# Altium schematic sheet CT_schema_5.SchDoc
size 367 x 245 mm
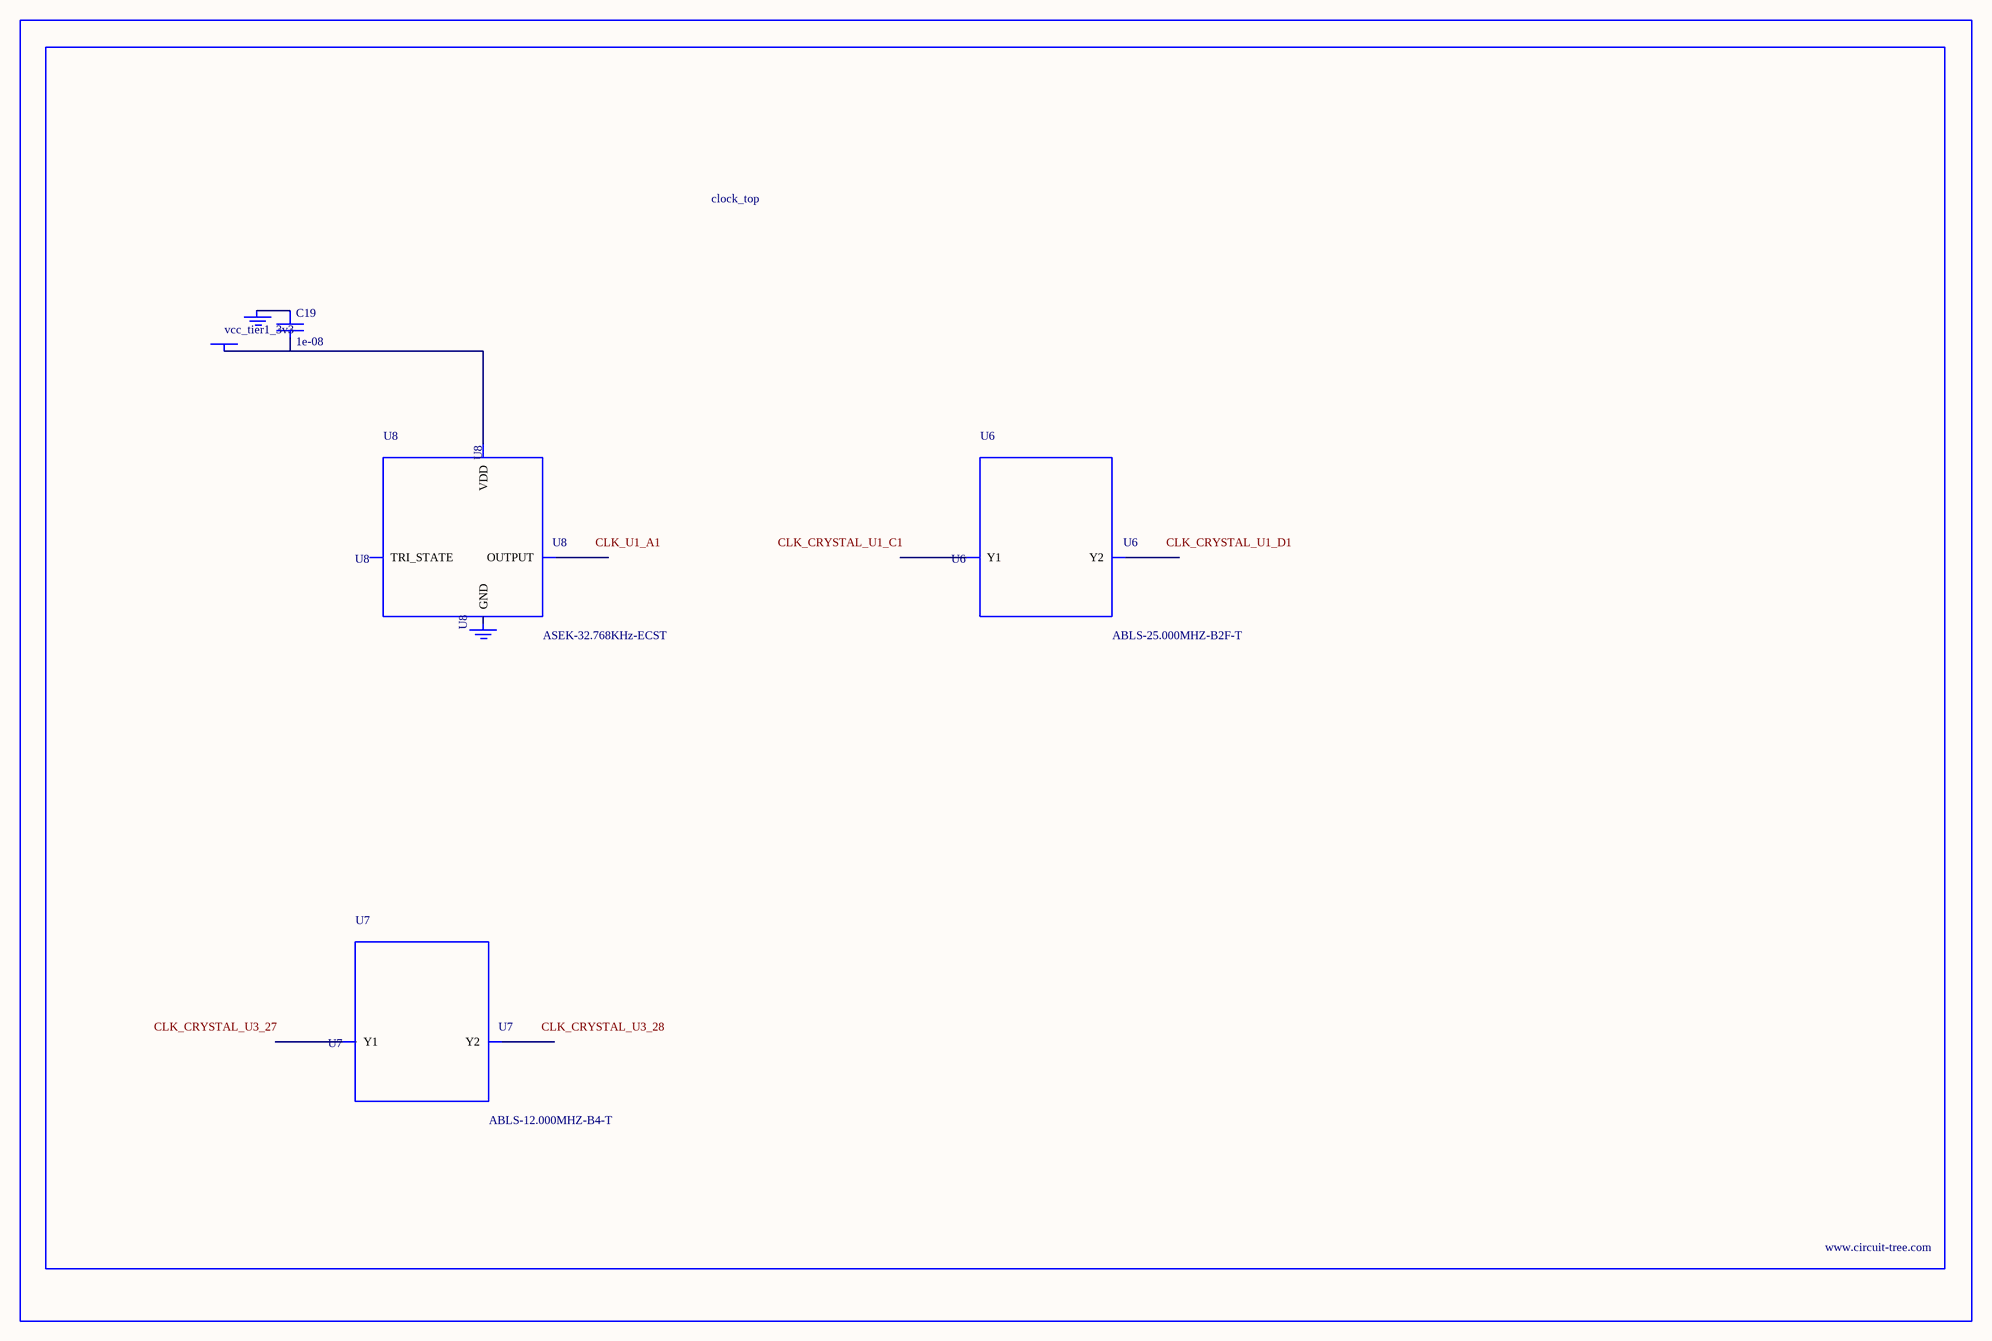
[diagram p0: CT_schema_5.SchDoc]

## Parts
BORDER4  (no value)
C19  1e-08  [C0402]
GND_INSTANCE_4_0  (no value)
GND_INSTANCE_4_1  (no value)
POWER_INSTANCE_4_0  vcc_tier1_3v3
U6  ABLS-25.000MHZ-B2F-T  [ABLS-25.000MHZ-B2F-T]
U7  ABLS-12.000MHZ-B4-T  [ABLS-12.000MHZ-B4-T]
U8  ASEK-32.768KHz-ECST  [ASEK]

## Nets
NetC19_1: C19.1 GND_INSTANCE_4_0.0(GND)
NetC19_2: C19.2 POWER_INSTANCE_4_0.0(PWR) U8.4(VDD)

Not connected (* = marked no-connect by the designer): GND_INSTANCE_4_1 0(GND); U6 1(Y1) 2(Y2); U7 1(Y1) 2(Y2); U8 1(TRI_STATE) 2(GND) 3(OUTPUT)

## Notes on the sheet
- Labels drawn without touching a wire or pin: CLK_CRYSTAL_U1_C1, CLK_CRYSTAL_U1_D1, CLK_CRYSTAL_U3_27, CLK_CRYSTAL_U3_28, CLK_U1_A1

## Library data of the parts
BORDER4 = BORDER_PAGE4
C19 = C0402C103K3RAC
GND_INSTANCE_4_0 GND_INSTANCE_4_1 = GND
POWER_INSTANCE_4_0 = PWR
